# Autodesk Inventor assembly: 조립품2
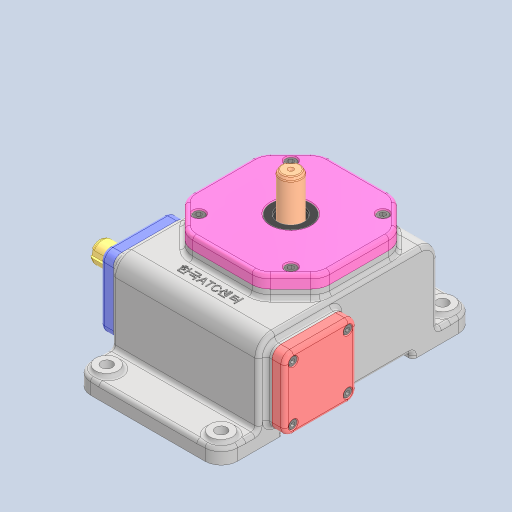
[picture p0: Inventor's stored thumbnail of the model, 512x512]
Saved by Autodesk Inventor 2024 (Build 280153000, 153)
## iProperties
Created: 2026-02
Part Number: 조립품2
Document SubType Name: Assembly
Designer: 2-10
Author: 2-10
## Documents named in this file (14)
- C:\Users\2-10\Desktop\760203V1005\조립품2.iam
- C:\Users\2-10\Desktop\760203V1005\하우징.ipt
- C:\Users\2-10\Desktop\760203V1005\6각 구멍붙이 볼트 M4x10.ipt
- C:\Users\2-10\Desktop\760203V1005\6각 구멍붙이 볼트 M5x10.ipt
- C:\Users\2-10\Desktop\760203V1005\뒷커버.ipt
- C:\Users\2-10\Desktop\760203V1005\앞커버.ipt
- C:\Users\2-10\Desktop\760203V1005\오일 실 17 32 8.ipt
- C:\Users\2-10\Desktop\760203V1005\웜 샤프트.ipt
- C:\Users\2-10\Desktop\760203V1005\웜 휠 커버.ipt
- C:\Users\2-10\Desktop\760203V1005\웜 휠.ipt
- C:\Users\2-10\Desktop\760203V1005\축.ipt
- C:\Users\2-10\Desktop\760203V1005\칼라.ipt
- C:\Users\2-10\Desktop\760203V1005\테이퍼 롤러 베어링 30203.ipt
- C:\Users\2-10\Desktop\760203V1005\평행 키 5x5x16.ipt
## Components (13 placed, 3 different names)
1. 하우징:1
2. 6각 구멍붙이 볼트 M4x10:1
3. 6각 구멍붙이 볼트 M5x10:1
4. 6각 구멍붙이 볼트 M4x10:2
5. 6각 구멍붙이 볼트 M4x10:3
6. 6각 구멍붙이 볼트 M4x10:4
7. 6각 구멍붙이 볼트 M4x10:5
8. 6각 구멍붙이 볼트 M4x10:6
9. 6각 구멍붙이 볼트 M4x10:7
10. 6각 구멍붙이 볼트 M4x10:8
11. 6각 구멍붙이 볼트 M5x10:2
12. 6각 구멍붙이 볼트 M5x10:3
13. 6각 구멍붙이 볼트 M5x10:4
